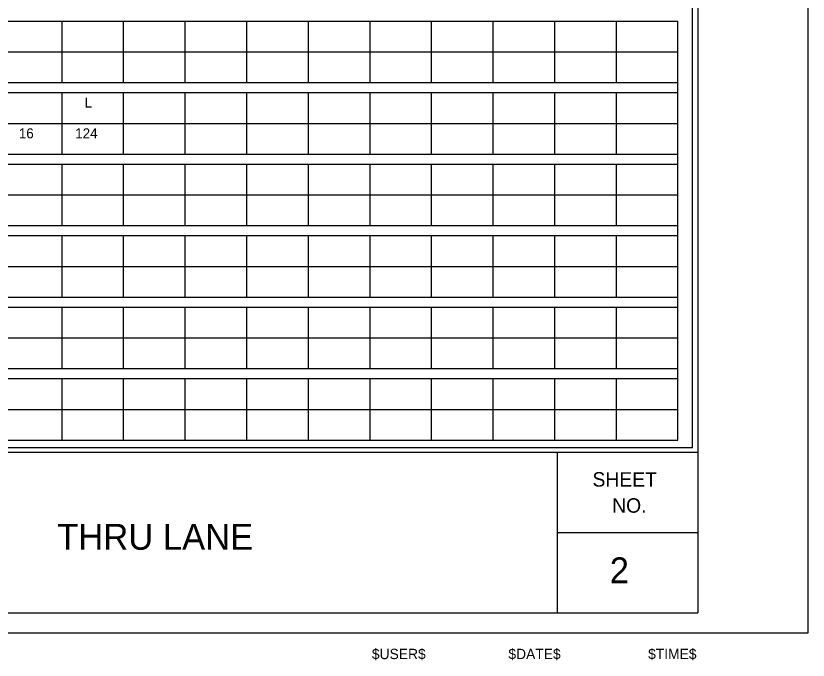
# Model space of a CAD drawing. Extents: x 122633 to 124574, y -23288 to -22025.
# Drawn here: x 124109.6 to 124574.1, y -23287.7 to -22909.7 of the extents above; entities that cross this region are included whole.
import ezdxf

# ---------------------------------------------------------------- set-up
doc = ezdxf.new("R2010")
doc.units = 0
for name, color, linetype in [('GSSign', 7, 'Continuous'), ('PlotBorder_dp', 7, 'Continuous'), ('SheetBorder_dp', 7, 'Continuous'), ('SheetLines_dp', 7, 'Continuous'), ('SheetLinesMisc2_dp', 7, 'Continuous'), ('TextMisc', 7, 'Continuous')]:
    doc.layers.add(name, color=color, linetype=linetype)

msp = doc.modelspace()

# ---------------------------------------------------------------- linework, layer by layer
at = {"layer": 'PlotBorder_dp'}
msp.add_lwpolyline([(122633.11, -23271.62), (124574.11, -23271.62), (124574.11, -22024.68), (122633.11, -22024.68)], close=True, dxfattribs=at)
at = {"layer": 'SheetBorder_dp'}
for p, q in [((124509.41, -22036.45), (124509.41, -23259.86)), ((122697.81, -23165.75), (124509.41, -23165.75)), ((122697.81, -23259.86), (124509.41, -23259.86))]:
    msp.add_line(p, q, dxfattribs=at)
at = {"layer": 'SheetLines_dp'}
for p, q in [((124427.06, -23259.86), (124427.06, -23165.75)), ((124427.06, -23212.81), (124509.41, -23212.81))]:
    msp.add_line(p, q, dxfattribs=at)
at = {"layer": 'SheetLinesMisc2_dp'}
for p, q in [((124506.27, -23162.98), (124506.27, -22039.23)), ((123609.8, -22912.77), (124497.63, -22912.77)), ((124136.47, -22912.77), (124136.47, -22948.85)), ((124172.58, -22912.77), (124172.58, -22948.85)), ((124208.7, -22912.77), (124208.7, -22948.85)), ((124244.82, -22912.77), (124244.82, -22948.85)), ((124280.94, -22912.77), (124280.94, -22948.85)), ((124317.05, -22912.77), (124317.05, -22948.85)), ((124353.16, -22912.77), (124353.16, -22948.85)), ((124389.29, -22912.77), (124389.29, -22948.85)), ((124425.4, -22912.77), (124425.4, -22948.85)), ((124461.52, -22912.77), (124461.52, -22948.85)), ((124497.63, -23158.6), (124497.63, -22912.77)), ((123609.8, -22930.8), (124497.63, -22930.8)), ((123609.8, -22948.85), (124497.63, -22948.85)), ((123609.8, -22954.73), (124497.63, -22954.73)), ((124136.47, -22954.73), (124136.47, -22990.8)), ((124172.58, -22954.73), (124172.58, -22990.8)), ((124208.7, -22954.73), (124208.7, -22990.8)), ((124244.82, -22954.73), (124244.82, -22990.8)), ((124280.94, -22954.73), (124280.94, -22990.8)), ((124317.05, -22954.73), (124317.05, -22990.8)), ((124353.16, -22954.73), (124353.16, -22990.8)), ((124389.29, -22954.73), (124389.29, -22990.8)), ((124425.4, -22954.73), (124425.4, -22990.8)), ((124461.52, -22954.73), (124461.52, -22990.8)), ((123609.8, -22972.77), (124497.63, -22972.77)), ((123609.8, -22990.8), (124497.63, -22990.8)), ((123609.8, -22996.68), (124497.63, -22996.68)), ((124136.47, -22996.68), (124136.47, -23032.75)), ((124172.58, -22996.68), (124172.58, -23032.75)), ((124208.7, -22996.68), (124208.7, -23032.75)), ((124244.82, -22996.68), (124244.82, -23032.75)), ((124280.94, -22996.68), (124280.94, -23032.75)), ((124317.05, -22996.68), (124317.05, -23032.75)), ((124353.16, -22996.68), (124353.16, -23032.75)), ((124389.29, -22996.68), (124389.29, -23032.75)), ((124425.4, -22996.68), (124425.4, -23032.75)), ((124461.52, -22996.68), (124461.52, -23032.75)), ((123609.8, -23014.71), (124497.63, -23014.71)), ((123609.8, -23032.75), (124497.63, -23032.75)), ((123609.8, -23038.63), (124497.63, -23038.63)), ((124136.47, -23038.63), (124136.47, -23074.71)), ((124172.58, -23038.63), (124172.58, -23074.71)), ((124208.7, -23038.63), (124208.7, -23074.71)), ((124244.82, -23038.63), (124244.82, -23074.71)), ((124280.94, -23038.63), (124280.94, -23074.71)), ((124317.05, -23038.63), (124317.05, -23074.71)), ((124353.16, -23038.63), (124353.16, -23074.71)), ((124389.29, -23038.63), (124389.29, -23074.71)), ((124425.4, -23038.63), (124425.4, -23074.71)), ((124461.52, -23038.63), (124461.52, -23074.71)), ((123609.8, -23056.66), (124497.63, -23056.66)), ((123609.8, -23074.71), (124497.63, -23074.71)), ((123609.8, -23080.59), (124497.63, -23080.59)), ((124136.47, -23080.59), (124136.47, -23116.66)), ((124172.58, -23080.59), (124172.58, -23116.66)), ((124208.7, -23080.59), (124208.7, -23116.66)), ((124244.82, -23080.59), (124244.82, -23116.66)), ((124280.94, -23080.59), (124280.94, -23116.66)), ((124317.05, -23080.59), (124317.05, -23116.66)), ((124353.16, -23080.59), (124353.16, -23116.66)), ((124389.29, -23080.59), (124389.29, -23116.66)), ((124425.4, -23080.59), (124425.4, -23116.66)), ((124461.52, -23080.59), (124461.52, -23116.66)), ((123609.8, -23098.63), (124497.63, -23098.63)), ((123609.8, -23116.66), (124497.63, -23116.66)), ((123609.8, -23122.54), (124497.63, -23122.54)), ((124136.47, -23122.54), (124136.47, -23158.6)), ((124172.58, -23122.54), (124172.58, -23158.6)), ((124208.7, -23122.54), (124208.7, -23158.6)), ((124244.82, -23122.54), (124244.82, -23158.6)), ((124280.94, -23122.54), (124280.94, -23158.6)), ((124317.05, -23122.54), (124317.05, -23158.6)), ((124353.16, -23122.54), (124353.16, -23158.6)), ((124389.29, -23122.54), (124389.29, -23158.6)), ((124425.4, -23122.54), (124425.4, -23158.6)), ((124461.52, -23122.54), (124461.52, -23158.6)), ((123609.8, -23140.57), (124497.63, -23140.57)), ((123609.8, -23158.6), (124497.63, -23158.6)), ((122701.01, -23162.98), (124506.26, -23162.98))]:
    msp.add_line(p, q, dxfattribs=at)

# ---------------------------------------------------------------- texts
at = {"layer": 'GSSign'}
for s, height, p in [('L', 5.88, (124149.82, -22963.53)), ('16', 5.882, (124111.31, -22981.57)), ('124', 5.882, (124144.36, -22981.57))]:
    msp.add_text(s, height=height, dxfattribs=at).set_placement(p)
at = {"layer": 'TextMisc'}
for s, p in [('SHEET', (124447.65, -23185.87)), ('NO.', (124459.18, -23201.16))]:
    msp.add_text(s, height=8.47, rotation=359.8607, dxfattribs=at).set_placement(p)
for s, height, p in [('THRU LANE', 15.164, (124133.81, -23222.93)), ('2', 15.16, (124457.79, -23242.58)), ('$USER$', 6.066, (124318.32, -23287.11)), ('$DATE$', 6.066, (124398.35, -23287.11)), ('$TIME$', 6.066, (124480.27, -23287.11))]:
    msp.add_text(s, height=height, dxfattribs=at).set_placement(p)

doc.saveas('drawing.dxf')
